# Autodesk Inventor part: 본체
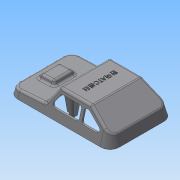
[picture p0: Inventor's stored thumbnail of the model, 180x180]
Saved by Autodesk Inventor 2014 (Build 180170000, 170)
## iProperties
Created: 2015-05
Part Number: 본체
Material: Generic
Document SubType Name: Modeling
Designer: Administrator
Density: 1 g/cm^3
Appearance: Default
Mass: 31.0398 g
Surface Area: 311.336 cm^2
Volume: 31.0398 cm^3
Author: Administrator
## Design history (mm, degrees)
sketch "스케치1"
  geometry: L1 (49, 38)-(-49, 38); L2 (-61, 26)-(-61, -26); L3 (-49, -38)-(49, -38); L4 (61, -26)-(61, 26); L5 (61, 38)-(-61, -38); L6 (-61, 38)-(61, -38); A1 r 12 centre (-49, 26) between (-49, 38) and (-61, 26); A2 r 12 centre (-49, -26) between (-61, -26) and (-49, -38); A3 r 12 centre (49, -26) between (49, -38) and (61, -26); A4 r 12 centre (49, 26) between (61, 26) and (49, 38); 1 further point
  constraints: 12 end point, 8 point on circle, 8 point on line, 8 tangent, 4 centre point, 3 equal radius, 2 midpoint, 2 parallel, 1 horizontal, 1 perpendicular
  dimensions: "d0" = 122 distance of L6.end L5.end; "d1" = 76 distance of L5.end L6.start; "d2" = 12 radius of A1
extrude "돌출1" new body sketch "스케치1" distance "d3" = 30; taper "d4" = -15 deg
sketch "스케치2"
  geometry: L1 (-31, 30)-(-61, 30); L2 (-61, 30)-(-61, 10); L3 (-61, 10)-(-31, 30); L4 (49, 30)-(-49, 30) reference; L5 (-52.962, 30)-(-49, 30) reference; L6 (-61, 0)-(-52.962, 30) reference; 1 further point
  constraints: 6 end point, 1 collinear, 1 horizontal, 1 perpendicular, 1 vertical alignment
  dimensions: "d5" = 30 distance of L1.start L1.end; "d6" = 20 distance of L1.end L2.end
extrude "돌출2" cut sketch "스케치2" stored distance "d7" = 30; taper "d8" = 0 deg
sketch "스케치6"
  geometry: L1 (6.628, 30)-(61, 30); L2 (61, 30)-(61, 8); L3 (19, 10.201)-(6.628, 30); L4 (49, 30)-(-31, 30) reference; L5 (61, 0)-(52.962, 30) reference; L6 (61, 8)-(19, 10.201); L7 (-49, 0)-(49, 0) reference; L8 (61, 0)-(49, 0) reference; 1 further point
  constraints: 8 end point, 1 collinear, 1 horizontal, 1 perpendicular, 1 vertical alignment
  dimensions: "d23" = 3 deg angle of L7 L6; "d24" = 125 deg angle of L3 L6; "d25" = 8 distance from line of L8 L2.end; "d26" = 42 distance from line of L3.start L2
extrude "돌출4" cut sketch "스케치6" stored distance "d27" = 30; taper "d28" = 0 deg
sketch "스케치7"
  geometry: L1 (-31.476, 48.267)-(-11.476, 48.267); L2 (-11.476, 48.267)-(-11.476, 22.267); L3 (-11.476, 22.267)-(-31.476, 22.267); L4 (-31.476, 22.267)-(-31.476, 48.267); L5 (-42.476, 61.267)-(-42.476, 9.267) reference; 2 further points
  constraints: 8 end point, 2 parallel, 1 horizontal, 1 horizontal alignment, 1 midpoint, 1 perpendicular
  dimensions: "d29" = 20 distance of L2.end L3.end; "d30" = 26 distance of L1.end L2.end; "d31" = 11 distance between parallel lines of L5 L4
extrude "돌출5" join sketch "스케치7" distance "d32" = 5; taper "d33" = -20 deg
fillet "모깎기2" dims "d35" = 3
feature "쉘1" dims "d36" = 2
sketch "스케치8"
  geometry: L1 (4.965, 30)-(-30.092, 30) reference; L2 (18.172, 11.526)-(7.51, 28.59) reference; L3 (-31.756, 29.496)-(-50.664, 16.891) reference; L4 (2.194, 25)-(-17.77, 25); L5 (10.362, 14.59)-(4.738, 23.59); L6 (7.818, 10)-(-17.77, 10); L7 (-20.77, 13)-(-20.77, 22); L8 (-30.242, 24.496)-(-43.742, 15.496); L9 (-26.986, 25)-(-28.578, 25); L10 (-42.078, 10)-(-26.986, 10); L11 (-23.986, 13)-(-23.986, 22); A1 r 3 centre (2.194, 22) between (4.738, 23.59) and (2.194, 25); A2 r 3 centre (7.818, 13) between (7.818, 10) and (10.362, 14.59); A3 r 3 centre (-17.77, 13) between (-20.77, 13) and (-17.77, 10); A4 r 3 centre (-17.77, 22) between (-17.77, 25) and (-20.77, 22); A5 r 3 centre (-26.986, 22) between (-23.986, 22) and (-26.986, 25); A6 r 3 centre (-28.578, 22) between (-28.578, 25) and (-30.242, 24.496); A7 r 3 centre (-26.986, 13) between (-26.986, 10) and (-23.986, 13); A8 r 3 centre (-42.078, 13) between (-43.742, 15.496) and (-42.078, 10); 7 further points
  constraints: 16 end point, 16 point on circle, 16 tangent, 12 point on line, 8 centre point, 7 equal radius, 6 parallel, 2 perpendicular, 1 collinear
  dimensions: "d37" = 5 distance between parallel lines of L2 L5; "d38" = 5 distance between parallel lines of L1 L4; "d39" = 34 distance of point (13.23, 10) point (-20.77, 10); "d40" = 15 distance of point (-20.77, 25) point (-20.77, 10); "d41" = 5 distance between parallel lines of L1 L9; "d42" = 5 distance between parallel lines of L3 L8; "d43" = 28 distance of point (-51.986, 10) point (-23.986, 10); "d44" = 15 distance of point (-23.986, 10) point (-23.986, 25); "d45" = 3 radius of A1
extrude "돌출6" cut sketch "스케치8" stored distance "d46" = 5; taper "d47" = 0 deg
sketch "스케치9"
  geometry: L1 (49, 38)-(-49, 38) reference; 1 further point
sketch "스케치10"
  geometry: L1 (61, -26)-(61, 26) reference; C1 r 3 at (0, 22); C2 r 3 at (40, 0); C3 r 3 at (0, -22); C4 r 3 at (-40, 0); 1 further point
  constraints: 4 centre point, 2 horizontal alignment, 2 vertical alignment
  dimensions: "d48" = 6 diameter of C1; "d49" = 6 diameter of C2; "d50" = 6 diameter of C3; "d51" = 6 diameter of C4; "d52" = 22 distance of C1.centre point (0, 0); "d53" = 44 distance of C1.centre C3.centre; "d54" = 40 distance of C4.centre point (0, 0); "d55" = 40 distance of C2.centre point (0, 0); "d56" = 21 distance from line of L1 C2.centre (derived)
extrude "돌출7" join sketch "스케치10" stored distance "d57" = 5; taper "d58" = 2 deg
node "작업 평면1"
sketch "스케치11"
  geometry: L1 (-34.994, 1)-(-44.994, 1); L2 (-44.994, 1)-(-44.994, -1); L3 (-44.994, -1)-(-34.994, -1); L4 (-34.994, -1)-(-34.994, 1); L5 (-34.994, 1)-(-44.994, -1); L6 (-44.994, 1)-(-34.994, -1); L7 (5, -23)-(-5, -23); L8 (-5, -23)-(-5, -21); L9 (-5, -21)-(5, -21); L10 (5, -21)-(5, -23); L11 (5, -23)-(-5, -21); L12 (-5, -23)-(5, -21); L13 (5, 23)-(-5, 23); L14 (-5, 23)-(-5, 21); L15 (-5, 21)-(5, 21); L16 (5, 21)-(5, 23); L17 (5, 23)-(-5, 21); L18 (-5, 23)-(5, 21); L19 (44.913, 1)-(34.913, 1); L20 (34.913, 1)-(34.913, -1); L21 (34.913, -1)-(44.913, -1); L22 (44.913, -1)-(44.913, 1); L23 (44.913, 1)-(34.913, -1); L24 (34.913, 1)-(44.913, -1); C1 r 3.978 at (0, 22) reference; C2 r 3.978 at (0, -22) reference; 3 further points; 2 other entities
  constraints: 48 end point, 8 midpoint, 8 parallel, 4 horizontal, 4 perpendicular, 2 other
  dimensions: "d60" = 10 distance of L3.end L2.end; "d61" = 2 distance of L2.end L1.end; "d62" = 10 distance of L8.end L9.end; "d63" = 2 distance of L7.end L8.end; "d64" = 10 distance of L15.end L14.end; "d65" = 2 distance of L14.end L13.end; "d66" = 10 distance of L21.end L20.end; "d67" = 2 distance of L20.end L19.end
extrude "돌출8" join sketch "스케치11" stored distance "d68" = 5; taper "d69" = 2.5 deg
sketch "스케치13"
  geometry: L1 (0.454, 26.025)-(3.233, 26.025) reference; L2 (0, 0)-(2.098, 0) reference; L3 (2.098, 0)-(3.233, 26.025) reference; L4 (46.098, -2.649)-(-51.902, -2.649) reference; L5 (-2.902, 26.025)-(6.686, 26.025); L6 (6.686, 26.025)-(2.098, 0); L7 (2.098, 0)-(-2.902, 0); L8 (-2.902, 0)-(-2.902, 26.025); 2 further points; 1 other entity
  constraints: 8 end point, 2 collinear, 2 parallel, 1 perpendicular, 1 vertical alignment, 1 other
  dimensions: "d76" = 100 deg angle of L6 L7; "d77" = 5 horizontal distance of L6.end point (-2.902, -1.082)
extrude "돌출10" join sketch "스케치13" stored distance "d78" = 5; taper "d79" = 0 deg
sketch "스케치14"
  geometry: L1 (0.035, 26.025)-(1.644, 26.025) reference; L2 (0, 0)-(2.098, 0) reference; L3 (0.035, 24.902)-(-10.628, 7.655) reference; L4 (5, 26.025)-(5, 0); L5 (5, 0)-(0, 0); L6 (0, 0)-(-3.409, 19.332); L7 (-3.409, 19.332)-(0.729, 26.025); L8 (0.729, 26.025)-(5, 26.025); 1 further point
  constraints: 10 end point, 4 collinear, 2 perpendicular, 1 parallel, 1 vertical alignment
  dimensions: "d80" = 100 deg angle of L5 L6; "d81" = 5 horizontal distance of L5.end point (5, -1.082)
extrude "돌출11" join sketch "스케치14" stored distance "d82" = 5; taper "d83" = 0 deg
node "작업 평면2"
sketch "스케치15"
  geometry: L1 (-26, 0)-(26, 0) reference; A1 r 4 centre (-21, 0) between (-17, 0) and (-25, 0); A2 r 4 centre (-10, 0) between (-6, 0) and (-14, 0); 1 further point
  constraints: 4 point on circle, 4 point on line, 2 centre point, 2 horizontal alignment
  dimensions: "d85" = 8 diameter of A1; "d86" = 8 diameter of A2; "d87" = 11 distance of A2.centre A1.centre; "d88" = 10 distance of point (0, 0) A2.centre
extrude "돌출12" join sketch "스케치15" stored distance "d89" = 5; taper "d90" = 0 deg
chamfer "모따기1" distance "d91" = 1; stored, may be unused: second distance "d92" = 2, angle "d93" = 45 deg
sketch "스케치16"
  geometry: L1 (-1.034, 23.7)-(1.791, 21.815) reference; L2 (0, 0)-(2.185, 0) reference; L3 (0.087, 0)-(-4.499, 26.012); L4 (-4.499, 26.012)-(5.087, 19.615); L5 (5.087, 19.615)-(5.087, 0); L6 (5.087, 0)-(0.087, 0); 3 further points; 2 other entities
  constraints: 8 end point, 2 collinear, 1 perpendicular, 1 vertical, 1 vertical alignment, 2 other
  dimensions: "d94" = 5 distance of L3.start L5.end; "d95" = 100 deg angle of L2 L3
extrude "돌출13" join sketch "스케치16" stored distance "d96" = 5; taper "d97" = 0 deg
sketch "스케치17"
  geometry: L1 (2.703, -15.875)-(0.327, -17.46) reference; L2 (2.01, 0)-(2.703, -15.875) reference; L3 (2.01, 0)-(0, 0) reference; L4 (-2.902, 0)-(2.098, 0); L5 (-2.902, -19.615)-(-2.902, 0); L6 (2.098, 0)-(4.666, -14.565); L7 (4.666, -14.565)-(-2.902, -19.615); 3 further points; 2 other entities
  constraints: 8 end point, 3 collinear, 1 horizontal, 1 vertical, 1 vertical alignment, 2 other
  dimensions: "d98" = 5 distance of L4.end L4.start; "d99" = 100 deg angle of L6 L3
extrude "돌출14" join sketch "스케치17" stored distance "d100" = 5; taper "d101" = 0 deg
sketch "스케치18"
  geometry: L1 (-0.429, 9.83)-(1.892, 9.952) reference; L2 (0, 0)-(2.091, 0) reference; L3 (4.994, 0)-(-0.006, 0); L4 (-0.006, 0)-(-1.728, 9.762); L5 (4.994, 10.114)-(4.994, 0); L6 (8.101, 10.277)-(1.892, 9.952) reference; L7 (-1.728, 9.762)-(4.994, 10.114); L8 (12.454, 11.955)-(12.454, 12.931) reference; L9 (-3.884, 11.1)-(12.454, 11.955) reference; L10 (-3.884, 12.075)-(-3.884, 11.1) reference; L11 (12.454, 12.931)-(-3.884, 12.075) reference; L12 (-3.884, 12.075)-(-3.884, 11.1) reference; L13 (-5.439, 5.937)-(-3.884, 11.1) reference; L14 (-5.439, 7.071)-(-5.439, 5.937) reference; L15 (-5.439, 7.071)-(-3.884, 12.075) reference; L16 (-2.381, 10.092)-(-2.381, 9.239) reference; L17 (-3.936, 5.088)-(-2.381, 10.092) reference; L18 (-3.936, 5.088)-(-3.936, 4.076) reference; L19 (-3.936, 4.076)-(-2.381, 9.239) reference; 19 further points; 9 other entities
  constraints: 8 end point, 4 collinear, 1 horizontal, 1 point on line, 1 vertical, 1 vertical alignment, 9 other
  dimensions: "d102" = 5 distance of L3.end L3.start; "d103" = 100 deg angle of L2 L4
  node "투영된 루프1"
  node "투영된 루프2"
  node "투영된 루프3"
  node "투영된 루프4"
sketch "스케치19"
  geometry: L1 (61, -26)-(61, 26) reference; 2 further points
  constraints: 1 horizontal alignment, 1 other
  dimensions: "d104" = 50 distance from line of point (11, 0) L1
feature "엠보싱1" sketch "스케치19" dims "d0" = 122, "d1" = 76, "d2" = 12, "d105" = 0.5, "d106" = 0
sketch "스케치21"
  geometry: L1 (-58.929, -26)-(-58.929, 26) reference; L2 (-49, 35.929)-(49, 35.929) reference; L3 (58.929, 26)-(58.929, -26) reference; L4 (49, -35.929)-(-49, -35.929) reference; L5 (59.929, -26)-(59.929, 26); L6 (49, 36.929)-(-49, 36.929); L7 (-59.929, 26)-(-59.929, -26); L8 (-49, -36.929)-(49, -36.929); A1 r 9.929 centre (-49, 26) between (-49, 35.929) and (-58.929, 26) reference; A2 r 9.929 centre (49, 26) between (58.929, 26) and (49, 35.929) reference; A3 r 9.929 centre (49, -26) between (49, -35.929) and (58.929, -26) reference; A4 r 9.929 centre (-49, -26) between (-58.929, -26) and (-49, -35.929) reference; A5 r 10.929 centre (49, 26) between (59.929, 26) and (49, 36.929); A6 r 10.929 centre (-49, 26) between (-49, 36.929) and (-59.929, 26); A7 r 10.929 centre (-49, -26) between (-59.929, -26) and (-49, -36.929); A8 r 10.929 centre (49, -26) between (49, -36.929) and (59.929, -26); 1 further point
  constraints: 8 end point, 8 point on circle, 4 centre point, 7 other
  dimensions: "d107" = 1 distance between parallel lines of L7 L1
extrude "돌출15" join sketch "스케치21" distance "d108" = 1; taper "d109" = 0 deg
extrude "돌출16" join sketch "스케치18" stored distance "d110" = 1; taper "d111" = 0 deg
sketch "스케치24"
  geometry: L1 (0.205, 10.277)-(-6.004, 9.952) reference; L2 (0, 0)-(2.104, 0) reference; L3 (-2.902, 0)-(2.098, 0); L4 (2.098, 0)-(3.74, 9.316); L5 (-2.902, 0)-(-2.902, 10.114); L6 (2.104, -0.087)-(2.558, 10.274) reference; L7 (-2.902, 10.114)-(3.264, 10.438); L8 (3.264, 9.948)-(3.264, 10.801) reference; L9 (3.264, 10.438)-(3.74, 9.316); 2 further points
  constraints: 10 end point, 4 collinear, 1 point on line, 1 vertical, 1 vertical alignment
  dimensions: "d112" = 100 deg angle of L4 L3; "d113" = 5 horizontal distance of L3.end point (-2.902, -2.042); "d124" = 110 deg angle of L9 L7
extrude "돌출17" join sketch "스케치24" stored distance "d114" = 1; taper "d115" = 0 deg
fillet "모깎기3" dims "d116" = 3
sketch "스케치25"
  geometry: C1 r 3 at (0, 0) reference; C2 r 3 at (-40, 22) reference; C3 r 3 at (-80, 0) reference; C4 r 3 at (-40, -22) reference; 5 further points
  constraints: 4 coincident
hole "구멍1" sketch "스케치25" at (-40, -22), (0, 0), (-40, 22), (-80, 0) diameter "d117" = 2.459; stored, may be unused: countersink angle "d121" = 90 deg, drill point angle "d123" = 118 deg; dims "d118" = 9, "d119" = 4, "d120" = 2, "d122" = 11
node "솔리드1"
mirror "대칭1"
mirror "대칭2"
node "투영된 루프5"
node "투영된 루프6"
node "투영된 루프7"
other parameters: "d59" = 2, "d84" = -63
